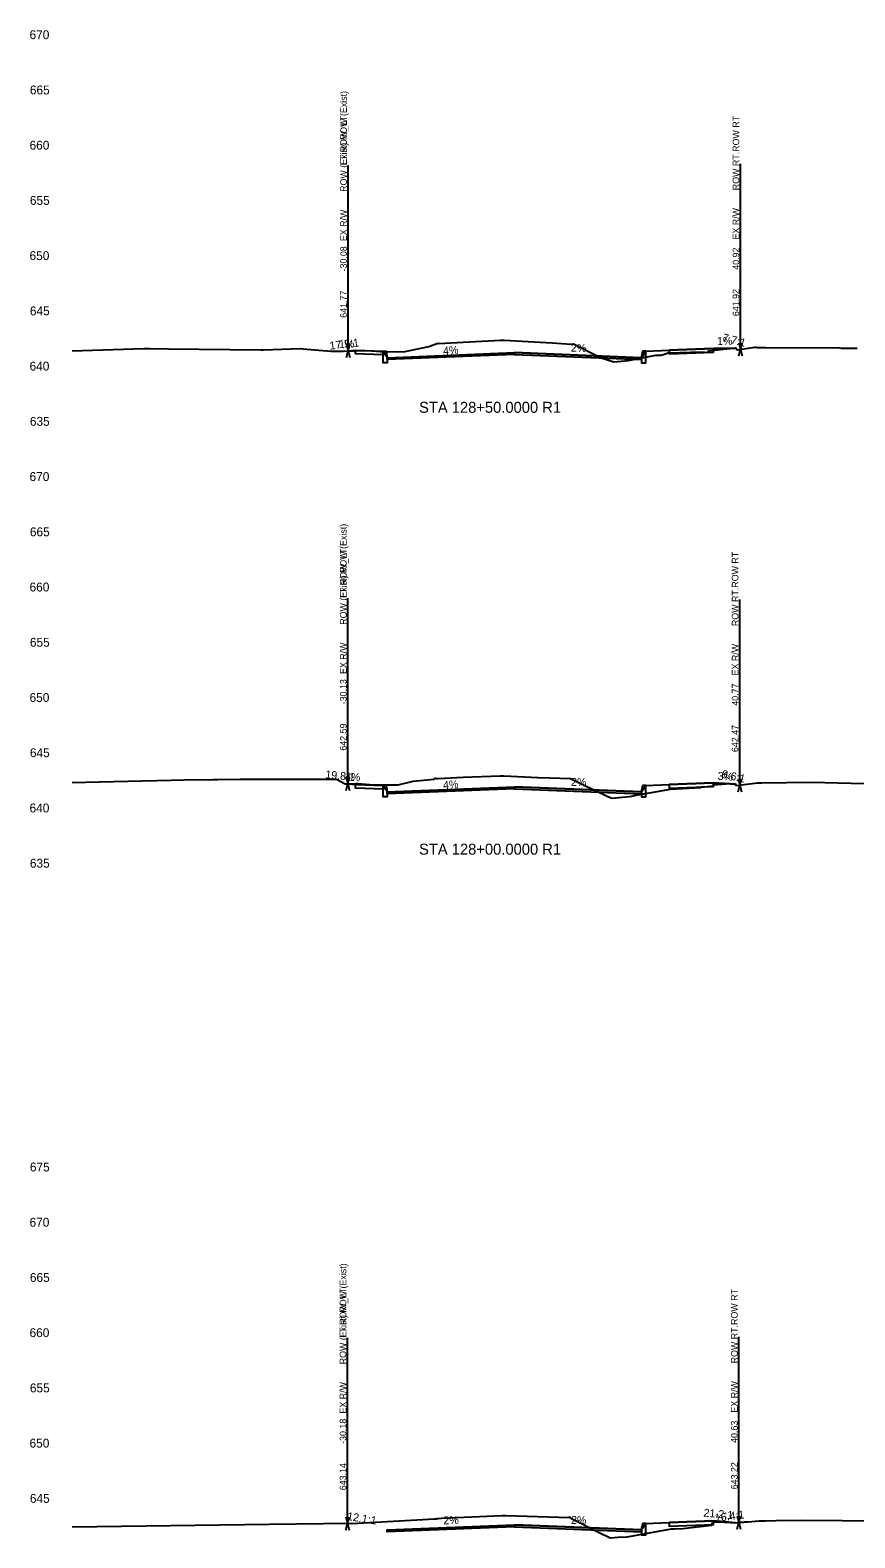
# Model space of a CAD drawing. Extents: x 2 to 741, y 16 to 2207.
# Drawn here: x 2.4 to 151.6, y 1933.7 to 2206.6 of the extents above; entities that cross this region are included whole.
import ezdxf

# ---------------------------------------------------------------- set-up
doc = ezdxf.new("R2010")
doc.units = 0
for name, color, linetype in [('Draft_XS_Feature_Name', 7, 'Continuous'), ('Draft_XS_Label', 7, 'Continuous'), ('Draft_XS_Point_Label_Indicator', 7, 'Continuous'), ('Draft_XS_Terminator', 7, 'Continuous'), ('Draft_XS_Text', 7, 'Continuous'), ('E_ROW', 7, 'Continuous'), ('E_Terrain_Exterior', 7, 'Continuous'), ('E_Terrain_Points_Low', 7, 'Continuous'), ('Grade_Veg_Grass', 7, 'Continuous'), ('P_XS_Sections', 7, 'Continuous'), ('Road_Curb', 7, 'Continuous'), ('Road_Pave_Asphalt', 7, 'Continuous'), ('Road_Sidewalk', 7, 'Continuous'), ('Terrain_Design', 7, 'Continuous')]:
    doc.layers.add(name, color=color, linetype=linetype)

msp = doc.modelspace()

# ---------------------------------------------------------------- linework, layer by layer
at = {"layer": 'Draft_XS_Terminator'}
for p, q in [((59.92, 2148.55), (59.92, 2170.55)), ((59.92, 2148.55), (59.92, 2170.55)), ((130.92, 2148.85), (130.92, 2170.85)), ((59.87, 2070.18), (59.87, 2092.18)), ((59.87, 2070.18), (59.87, 2092.18)), ((130.77, 2069.93), (130.77, 2091.93)), ((59.82, 1936.28), (59.82, 1958.28)), ((59.82, 1936.28), (59.82, 1958.28)), ((130.63, 1936.45), (130.63, 1958.45))]:
    msp.add_line(p, q, dxfattribs=at)
at = {"layer": 'E_ROW'}
for p, q in [((59.92, 2148.55), (59.92, 2182.15)), ((59.92, 2148.55), (59.92, 2182.15)), ((130.92, 2148.85), (130.92, 2182.45)), ((59.62, 2147.35), (60.22, 2149.75)), ((59.62, 2149.75), (60.22, 2147.35)), ((59.62, 2147.35), (60.22, 2149.75)), ((59.62, 2149.75), (60.22, 2147.35)), ((130.62, 2147.65), (131.22, 2150.05)), ((130.62, 2150.05), (131.22, 2147.65)), ((59.87, 2070.18), (59.87, 2103.78)), ((59.87, 2070.18), (59.87, 2103.78)), ((130.77, 2069.93), (130.77, 2103.53)), ((59.57, 2068.98), (60.17, 2071.38)), ((59.57, 2071.38), (60.17, 2068.98)), ((59.57, 2068.98), (60.17, 2071.38)), ((59.57, 2071.38), (60.17, 2068.98)), ((130.47, 2068.73), (131.07, 2071.13)), ((130.47, 2071.13), (131.07, 2068.73)), ((59.82, 1936.28), (59.82, 1969.88)), ((59.82, 1936.28), (59.82, 1969.88)), ((130.63, 1936.45), (130.63, 1970.05)), ((59.52, 1935.08), (60.12, 1937.48)), ((59.52, 1937.48), (60.12, 1935.08)), ((59.52, 1935.08), (60.12, 1937.48)), ((59.52, 1937.48), (60.12, 1935.08)), ((130.33, 1935.25), (130.93, 1937.65)), ((130.33, 1937.65), (130.93, 1935.25))]:
    msp.add_line(p, q, dxfattribs=at)
at = {"layer": 'E_Terrain_Exterior'}
for points in [[(10, 2148.6), (22.94, 2149), (23.14, 2149.01), (23.25, 2149.01), (23.84, 2149), (23.98, 2149), (27.42, 2148.96), (38.49, 2148.84), (44.17, 2148.78), (44.62, 2148.78), (51.3, 2148.99), (51.37, 2148.97), (51.7, 2148.95), (56.77, 2148.49), (56.81, 2148.49), (57.63, 2148.5), (57.81, 2148.5), (57.99, 2148.51), (58.57, 2148.52), (58.98, 2148.53), (63.47, 2148.63), (65.71, 2148.48), (69.95, 2148.41), (74.51, 2149.38), (76.15, 2149.94), (76.24, 2149.91), (84.13, 2150.35), (87.45, 2150.5), (87.64, 2150.5), (88.14, 2150.5), (96.8, 2150.05), (100.27, 2149.78), (100.56, 2149.8), (100.66, 2149.84), (105.68, 2147.28), (107.97, 2146.57), (110.65, 2146.83), (115.56, 2147.77), (116.54, 2147.8), (117.81, 2148.22), (123.93, 2148.38), (125, 2148.26), (125.1, 2148.59), (125.11, 2148.6), (125.13, 2148.6), (126.13, 2148.68), (126.2, 2148.68), (130.08, 2149.09), (130.28, 2148.76), (133.53, 2149.22), (133.67, 2149.21), (133.91, 2149.2), (134.14, 2149.19), (134.19, 2149.19), (134.39, 2149.18), (134.73, 2149.17), (134.82, 2149.17), (135.5, 2149.18), (148.81, 2149.09), (149.13, 2149.08), (152.03, 2149.04)], [(10, 2070.42), (14.83, 2070.54), (27.89, 2070.85), (30.15, 2070.91), (35.44, 2070.98), (36.31, 2070.99), (40.4, 2071), (51.08, 2071.02), (57.8, 2071.01), (59.37, 2070.18), (59.43, 2070.17), (60.3, 2070.19), (61.36, 2070.21), (61.74, 2070.22), (64.49, 2070.01), (66.69, 2069.97), (68.98, 2070.02), (71.7, 2070.67), (75.48, 2071.04), (75.74, 2071.19), (75.9, 2071.16), (76.18, 2071.16), (80.73, 2071.41), (87.41, 2071.65), (87.56, 2071.65), (87.88, 2071.64), (88.1, 2071.64), (94.32, 2071.31), (96.44, 2071.25), (100.17, 2071.13), (100.17, 2071.17), (100.25, 2071.11), (101.74, 2070.34), (107.54, 2067.56), (110.8, 2067.91), (111.23, 2067.95), (112, 2068.1), (118.23, 2069.21), (123.72, 2069.5), (123.85, 2069.63), (124.32, 2069.65), (125.95, 2069.82), (125.99, 2070), (129.08, 2070.25), (129.74, 2070.19), (129.95, 2070.2), (130.15, 2069.86), (134, 2070.33), (134.1, 2070.33), (134.46, 2070.36), (134.48, 2070.36), (134.79, 2070.37), (143.73, 2070.47), (155.72, 2070.15)], [(10, 1935.68), (45.61, 1936.13), (60.38, 1936.29), (60.57, 1936.28), (75.52, 1937.08), (75.85, 1937.11), (76.03, 1937.14), (76.17, 1937.16), (76.83, 1937.22), (87.8, 1937.71), (87.83, 1937.71), (88.44, 1937.68), (99.97, 1937.32), (99.98, 1937.47), (100.22, 1937.25), (105.2, 1934.68), (107.34, 1933.66), (108.74, 1933.81), (110.4, 1933.84), (117.77, 1935.15), (118.44, 1935.27), (118.94, 1935.3), (118.95, 1935.31), (120.47, 1935.36), (125.7, 1935.93), (125.83, 1936.49), (126.95, 1936.58), (129.08, 1936.41), (129.73, 1936.44), (129.79, 1936.35), (130.8, 1936.47), (130.83, 1936.47), (130.92, 1936.48), (131.01, 1936.49), (131.12, 1936.49), (131.27, 1936.5), (131.47, 1936.52), (131.48, 1936.52), (131.66, 1936.53), (131.89, 1936.55), (132.31, 1936.58), (132.95, 1936.63), (133.55, 1936.67), (133.61, 1936.67), (134.31, 1936.72), (135.42, 1936.76), (137.34, 1936.83), (141.7, 1936.86), (156.9, 1936.73)]]:
    msp.add_lwpolyline(points, dxfattribs=at)
at = {"layer": 'Grade_Veg_Grass'}
for points in [[(59.25, 2148.53), (59.25, 2148.53), (61.25, 2148.7)], [(113.75, 2148.5), (118, 2148.67)], [(130, 2149.08), (126, 2148.99), (126, 2148.99)], [(59.25, 2070.24), (61.25, 2070.08), (61.25, 2070.08)], [(113.75, 2069.88), (118, 2070.05)], [(130, 2070.11), (130, 2070.11), (126, 2070.37)], [(113.75, 1936.26), (118, 1936.43)], [(130, 1936.37), (130, 1936.37), (126, 1936.75)]]:
    msp.add_lwpolyline(points, dxfattribs=at)
at = {"layer": 'Road_Curb'}
for points in [[(67, 2147.33), (67, 2146.42), (66.25, 2146.42), (66.25, 2148.5), (66.77, 2148.5), (67, 2147.33)], [(113, 2147.33), (113, 2146.42), (113.75, 2146.42), (113.75, 2148.5), (113.23, 2148.5), (113, 2147.33)], [(67, 2068.71), (67, 2067.8), (66.25, 2067.8), (66.25, 2069.88), (66.77, 2069.88), (67, 2068.71)], [(113, 2068.71), (113, 2067.8), (113.75, 2067.8), (113.75, 2069.88), (113.23, 2069.88), (113, 2068.71)], [(113, 1935.09), (113, 1934.18), (113.75, 1934.18), (113.75, 1936.26), (113.23, 1936.26), (113, 1935.09)]]:
    msp.add_lwpolyline(points, dxfattribs=at)
at = {"layer": 'Road_Pave_Asphalt'}
for points in [[(90, 2148.25), (90, 2147.92), (67, 2147), (67, 2147.33), (90, 2148.25)], [(90, 2148.25), (90, 2147.92), (113, 2147), (113, 2147.33), (90, 2148.25)], [(90, 2069.63), (90, 2069.3), (67, 2068.38), (67, 2068.71), (90, 2069.63)], [(90, 2069.63), (90, 2069.3), (113, 2068.38), (113, 2068.71), (90, 2069.63)], [(90, 1936.01), (90, 1935.68), (67, 1934.76), (67, 1935.09), (90, 1936.01)], [(90, 1936.01), (90, 1935.68), (113, 1934.76), (113, 1935.09), (90, 1936.01)]]:
    msp.add_lwpolyline(points, dxfattribs=at)
at = {"layer": 'Road_Sidewalk'}
for points in [[(66.25, 2148.5), (66.25, 2147.83), (61.25, 2148.03), (61.25, 2148.7), (66.25, 2148.5)], [(118, 2148.67), (118, 2148), (126, 2148.32), (126, 2148.99), (118, 2148.67)], [(66.25, 2069.88), (66.25, 2069.21), (61.25, 2069.41), (61.25, 2070.08), (66.25, 2069.88)], [(118, 2070.05), (118, 2069.38), (126, 2069.7), (126, 2070.37), (118, 2070.05)], [(118, 1936.43), (118, 1935.76), (126, 1936.08), (126, 1936.75), (118, 1936.43)]]:
    msp.add_lwpolyline(points, dxfattribs=at)
at = {"layer": 'Terrain_Design'}
for points in [[(59.25, 2148.53), (59.25, 2148.53), (61.25, 2148.7), (66.25, 2148.5), (66.77, 2148.5), (67, 2147.33), (90, 2148.25), (113, 2147.33), (113.23, 2148.5), (113.75, 2148.5), (118, 2148.67), (126, 2148.99), (130, 2149.08)], [(59.25, 2148.53), (59.25, 2148.53), (61.25, 2148.7), (66.25, 2148.5), (66.77, 2147.69), (67, 2147.33), (90, 2148.25), (113, 2147.33), (113.23, 2147.69), (113.75, 2148.5), (118, 2148.67), (126, 2148.99), (130, 2149.08)], [(59.25, 2070.24), (59.25, 2070.24), (61.25, 2070.08), (66.25, 2069.88), (66.77, 2069.88), (67, 2068.71), (90, 2069.63), (113, 2068.71), (113.23, 2069.88), (113.75, 2069.88), (118, 2070.05), (126, 2070.37), (130, 2070.11)], [(59.25, 2070.24), (59.25, 2070.24), (61.25, 2070.08), (66.25, 2069.88), (66.77, 2069.07), (67, 2068.71), (90, 2069.63), (113, 2068.71), (113.23, 2069.07), (113.75, 2069.88), (118, 2070.05), (126, 2070.37), (130, 2070.11)], [(67, 1935.09), (90, 1936.01), (113, 1935.09), (113.23, 1936.26), (113.75, 1936.26), (118, 1936.43), (126, 1936.75), (130, 1936.37)], [(67, 1935.09), (90, 1936.01), (113, 1935.09), (113.23, 1935.45), (113.75, 1936.26), (118, 1936.43), (126, 1936.75), (130, 1936.37)]]:
    msp.add_lwpolyline(points, dxfattribs=at)

# ---------------------------------------------------------------- texts
at = {"layer": 'Draft_XS_Feature_Name'}
for s, p in [('ROW (Exist).ROW (Exist)', (59.68, 2177.35)), ('ROW_LT.ROW_LT', (59.68, 2177.35)), ('ROW RT.ROW RT', (130.68, 2177.65)), ('ROW (Exist).ROW (Exist)', (59.63, 2098.98)), ('ROW_LT.ROW_LT', (59.63, 2098.98)), ('ROW RT.ROW RT', (130.53, 2098.73)), ('ROW (Exist).ROW (Exist)', (59.58, 1965.08)), ('ROW_LT.ROW_LT', (59.58, 1965.08)), ('ROW RT.ROW RT', (130.39, 1965.25))]:
    msp.add_text(s, height=1.2, rotation=90, dxfattribs=at).set_placement(p)
at = {"layer": 'Draft_XS_Label'}
for s, p in [('-30.08', (59.68, 2162.95)), ('-30.08', (59.68, 2162.95)), ('40.92', (130.68, 2163.25)), ('641.77', (59.68, 2154.55)), ('641.77', (59.68, 2154.55)), ('641.92', (130.68, 2154.85)), ('-30.13', (59.63, 2084.58)), ('-30.13', (59.63, 2084.58)), ('40.77', (130.53, 2084.33)), ('642.59', (59.63, 2076.18)), ('642.59', (59.63, 2076.18)), ('642.47', (130.53, 2075.93)), ('-30.18', (59.58, 1950.68)), ('-30.18', (59.58, 1950.68)), ('40.63', (130.39, 1950.85)), ('643.14', (59.58, 1942.28)), ('643.14', (59.58, 1942.28)), ('643.22', (130.39, 1942.45))]:
    msp.add_text(s, height=1.2, rotation=90, dxfattribs=at).set_placement(p)
at = {"layer": 'Draft_XS_Point_Label_Indicator'}
for p in [(59.24, 2148.52), (61.24, 2148.69), (66.24, 2148.49), (66.76, 2148.49), (113.22, 2148.49), (113.74, 2148.49), (117.99, 2148.66), (125.99, 2148.98), (129.99, 2149.07), (66.99, 2147.32), (66.99, 2146.4), (112.99, 2147.32), (112.99, 2146.4), (59.24, 2070.23), (61.24, 2070.07), (66.24, 2069.87), (66.76, 2069.87), (113.22, 2069.87), (113.74, 2069.87), (117.99, 2070.04), (125.99, 2070.36), (129.99, 2070.1), (66.99, 2068.7), (66.99, 2067.78), (112.99, 2068.7), (112.99, 2067.78), (113.22, 1936.25), (113.74, 1936.25), (117.99, 1936.42), (125.99, 1936.74), (129.99, 1936.36), (66.99, 1935.08), (112.99, 1935.08), (112.99, 1934.16)]:
    msp.add_text('X', height=0.024, dxfattribs=at).set_placement(p)
at = {"layer": 'Draft_XS_Text'}
for s, height, p in [('670', 1.608, (2.26, 2205)), ('665', 1.608, (2.32, 2195)), ('660', 1.608, (2.26, 2185)), ('655', 1.608, (2.32, 2175)), ('650', 1.608, (2.26, 2165)), ('645', 1.608, (2.32, 2155)), ('640', 1.608, (2.26, 2145)), ('STA 128+50.0000 R1', 1.992, (72.74, 2137.35)), ('635', 1.608, (2.32, 2135)), ('670', 1.608, (2.26, 2125)), ('665', 1.608, (2.32, 2115)), ('660', 1.608, (2.26, 2105)), ('655', 1.608, (2.32, 2095)), ('650', 1.608, (2.26, 2085)), ('645', 1.608, (2.32, 2075)), ('640', 1.608, (2.26, 2065)), ('STA 128+00.0000 R1', 1.992, (72.74, 2057.35)), ('635', 1.608, (2.32, 2055)), ('675', 1.608, (2.32, 2000)), ('670', 1.608, (2.26, 1990)), ('665', 1.608, (2.32, 1980)), ('660', 1.608, (2.26, 1970)), ('655', 1.608, (2.32, 1960)), ('650', 1.608, (2.26, 1950)), ('645', 1.608, (2.32, 1940))]:
    msp.add_text(s, height=height, dxfattribs=at).set_placement(p)
for s, rotation, p in [('1%', 1.3328, (126.67, 2149.61)), ('7.7:1', 345.5078, (127.51, 2150.35)), ('17.5:1', 6.5277, (56.63, 2148.77)), ('1%', 1.3561, (58.26, 2149.11)), ('4%', 4.5657, (77.14, 2147.83)), ('2%', 357.7094, (100.21, 2148.45)), ('19.8:1', 354.2454, (55.73, 2071.2)), ('4%', 355.9872, (59.29, 2070.82)), ('3%', 356.3315, (126.73, 2070.92)), ('8.6:1', 346.9066, (127.41, 2071.33)), ('4%', 4.5657, (77.14, 2069.21)), ('2%', 357.7094, (100.21, 2069.83)), ('12.1:1', 350.6144, (59.65, 1936.92)), ('21.2:1', 354.6148, (124.16, 1937.53)), ('16.4:1', 6.935, (126.36, 1936.53)), ('2%', 2.2906, (77.16, 1936.1)), ('2%', 357.7094, (100.21, 1936.21))]:
    msp.add_text(s, height=1.44, rotation=rotation, dxfattribs=at).set_placement(p)
at = {"layer": 'E_ROW'}
for p in [(59.68, 2168.43), (59.68, 2168.43), (130.68, 2168.73), (59.63, 2090.06), (59.63, 2090.06), (130.53, 2089.81), (59.58, 1956.16), (59.58, 1956.16), (130.39, 1956.33)]:
    msp.add_text('EX R/W', height=1.2, rotation=90, dxfattribs=at).set_placement(p)
at = {"layer": 'E_Terrain_Points_Low'}
for p in [(89.99, 2148.24), (89.99, 2069.62), (89.99, 1936)]:
    msp.add_text('X', height=0.024, dxfattribs=at).set_placement(p)
at = {"layer": 'P_XS_Sections'}
for p in [(10, 2135), (10, 2055)]:
    msp.add_text('-', height=0.0001, dxfattribs=at).set_placement(p)

doc.saveas('drawing.dxf')
